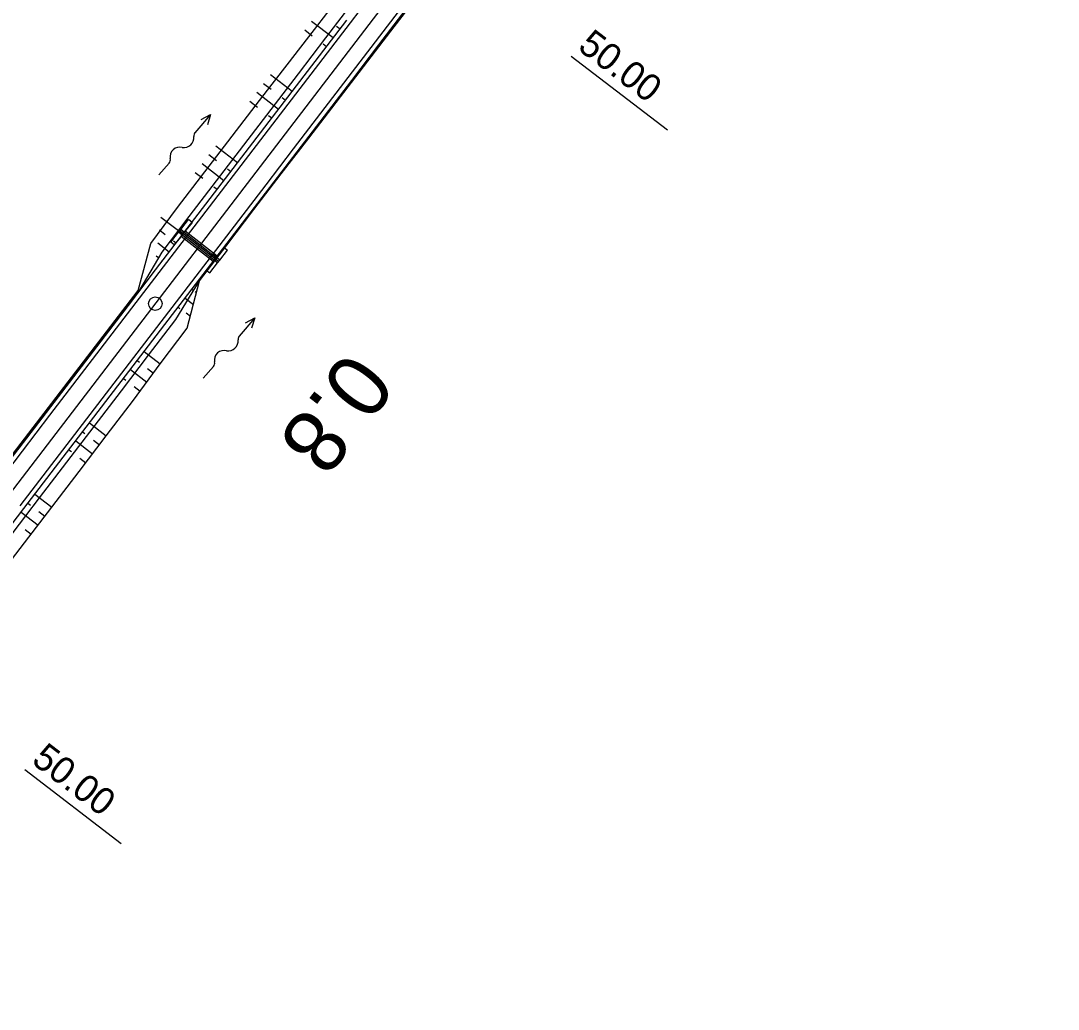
# Model space of a CAD drawing. Extents: x -481645 to -478728, y -1113199 to -1110710.
# Drawn here: x -479367.1 to -479251.7, y -1111289 to -1111179 of the extents above; entities that cross this region are included whole.
import ezdxf

# ---------------------------------------------------------------- set-up
doc = ezdxf.new("R2010")
doc.units = 0
for name, color, linetype in [('CP14_HATCH_SLOPE_L', 7, 'Continuous'), ('CP14_HECTOMETRY', 7, 'Continuous'), ('CP14_HLBODY', 7, 'Continuous'), ('CP14_ZPEVKRAJ', 7, 'Continuous'), ('CP1_HECTOMETRY', 7, 'Continuous'), ('O6_HATCH_SLOPE_L', 7, 'Continuous'), ('O6_HATCH_SLOPE_R', 7, 'Continuous'), ('O6_HLBODY', 7, 'Continuous'), ('O6_HRANA_TELESO', 7, 'Continuous'), ('O6_OSA', 7, 'Continuous'), ('O6_VOZOVKA', 7, 'Continuous'), ('O6_ZPEVKRAJ', 7, 'Continuous')]:
    doc.layers.add(name, color=color, linetype=linetype)

# ---------------------------------------------------------------- blocks, each defined once
blk = doc.blocks.new('A$C70B')
at = {"layer": 'CP14_HLBODY'}
for p, q in [((0.87, 0), (-0.87, 0)), ((6.86, 0.43), (7.97, 0)), ((7.97, 0), (5.28, 0)), ((7.97, 0), (6.86, -0.48))]:
    blk.add_line(p, q, dxfattribs=at)
for centre, radius, start, end in [((0.87, 0.58), 0.582, 269.6924, 322.7901), ((2.17, -0.42), 1.05, 24.4039, 142.0836), ((4.08, 0.59), 1.11, 210.8873, 317.3707), ((5.32, -0.64), 0.636, 85.9766, 131.7248)]:
    blk.add_arc(centre, radius, start, end, dxfattribs=at)
blk = doc.blocks.new('A$C716')
at = {"layer": 'CP14_ZPEVKRAJ'}
for p, q in [((-5.015, 2.333), (-4.471, 3.623)), ((-4.01, 3.428), (-4.471, 3.623)), ((-5.17, 1.964), (-5.015, 2.333)), ((-5.015, 2.333), (-0.383, 0.379)), ((-4.554, 2.138), (-5.015, 2.333)), ((-4.01, 3.428), (-4.554, 2.138)), ((-5.715, 0.674), (-5.17, 1.964)), ((-4.71, 1.77), (-5.254, 0.48)), ((-0.078, -0.184), (-5.171, 1.964)), ((-4.71, 1.77), (-5.17, 1.964)), ((0, 0), (-5.093, 2.148)), ((-4.768, 1.632), (-0.597, -0.128)), ((-0.325, 0.517), (-4.496, 2.277)), ((0.161, 1.669), (-0.383, 0.379)), ((0.078, 0.184), (0.622, 1.474)), ((0.161, 1.669), (0.622, 1.474)), ((-5.254, 0.48), (-5.715, 0.674)), ((-0.538, 0.01), (-1.083, -1.28)), ((-0.078, -0.184), (-0.999, 0.204)), ((0.078, 0.184), (-0.844, 0.573)), ((-0.538, 0.01), (-0.383, 0.379)), ((-0.078, -0.184), (0.078, 0.184)), ((-0.622, -1.474), (-0.078, -0.184)), ((-1.083, -1.28), (-0.622, -1.474))]:
    blk.add_line(p, q, dxfattribs=at)

msp = doc.modelspace()

# ---------------------------------------------------------------- linework, layer by layer
at = {"layer": 'CP14_HATCH_SLOPE_L'}
for p, q in [((-479325.29, -1111179.1), (-479325.23, -1111179.15)), ((-479325.18, -1111179.19), (-479325.18, -1111179.19)), ((-479329.09, -1111184.07), (-479328.99, -1111184.14)), ((-479329.85, -1111185.06), (-479329.8, -1111185.1)), ((-479329.75, -1111185.14), (-479329.75, -1111185.14)), ((-479331.37, -1111187.04), (-479331.32, -1111187.08)), ((-479330.61, -1111186.05), (-479330.51, -1111186.13)), ((-479331.27, -1111187.12), (-479331.27, -1111187.12)), ((-479335.17, -1111192.01), (-479335.08, -1111192.07)), ((-479336.69, -1111193.99), (-479336.6, -1111194.06)), ((-479335.93, -1111193), (-479335.88, -1111193.03)), ((-479335.84, -1111193.06), (-479335.84, -1111193.06)), ((-479337.45, -1111194.99), (-479337.41, -1111195.02)), ((-479337.36, -1111195.05), (-479337.36, -1111195.05)), ((-479342.01, -1111200.94), (-479341.97, -1111200.97)), ((-479341.24, -1111199.95), (-479341.17, -1111200.01)), ((-479342.77, -1111201.93), (-479342.68, -1111201.99)), ((-479341.93, -1111201), (-479341.93, -1111201)), ((-479343.53, -1111202.93), (-479343.48, -1111202.96)), ((-479343.44, -1111202.99), (-479343.44, -1111202.99)), ((-479348.08, -1111208.88), (-479347.99, -1111208.95)), ((-479347.32, -1111207.89), (-479347.23, -1111207.96)), ((-479348.84, -1111209.87), (-479347.91, -1111210.59)), ((-479347.73, -1111209.15), (-479347.57, -1111209.27)), ((-479349.6, -1111210.87), (-479349.41, -1111211.02)), ((-479348.73, -1111211.53), (-479348.25, -1111211.9)), ((-479353.4, -1111215.83), (-479351.6, -1111217.2)), ((-479354.16, -1111216.82), (-479353.91, -1111217.02)), ((-479354.92, -1111217.81), (-479353.09, -1111219.22)), ((-479353, -1111217.71), (-479352.35, -1111218.21)), ((-479355.68, -1111218.81), (-479355.42, -1111219.01)), ((-479354.49, -1111219.72), (-479353.83, -1111220.23)), ((-479359.48, -1111223.77), (-479357.6, -1111225.21)), ((-479360.24, -1111224.76), (-479359.98, -1111224.96)), ((-479361, -1111225.76), (-479359.12, -1111227.19)), ((-479359.04, -1111225.68), (-479358.36, -1111226.2)), ((-479361.76, -1111226.75), (-479361.49, -1111226.95)), ((-479360.55, -1111227.67), (-479359.88, -1111228.19)), ((-479365.56, -1111231.71), (-479363.68, -1111233.15)), ((-479366.32, -1111232.7), (-479366.05, -1111232.91)), ((-479367.08, -1111233.7), (-479365.19, -1111235.14)), ((-479365.11, -1111233.63), (-479364.43, -1111234.15)), ((-479366.63, -1111235.61), (-479365.95, -1111236.13))]:
    msp.add_line(p, q, dxfattribs=at)
at = {"layer": 'CP1_HECTOMETRY'}
msp.add_line((-479472.65, -1111367.92), (-479250.4, -1111077.57), dxfattribs=at)
at = {"layer": 'O6_HATCH_SLOPE_L'}
msp.add_circle((-479352.15, -1111210.49), 0.75, dxfattribs=at)
at = {"layer": 'O6_HATCH_SLOPE_R'}
for p, q in [((-479334.69, -1111180.71), (-479335.53, -1111180.07)), ((-479332.35, -1111180.93), (-479334.77, -1111179.08)), ((-479331.59, -1111179.94), (-479331.97, -1111179.65)), ((-479333.11, -1111181.92), (-479333.49, -1111181.63)), ((-479336.91, -1111186.88), (-479339.33, -1111185.03)), ((-479338.43, -1111188.87), (-479340.86, -1111187.01)), ((-479339.26, -1111186.66), (-479340.1, -1111186.02)), ((-479340.78, -1111188.65), (-479341.62, -1111188)), ((-479337.67, -1111187.88), (-479338.04, -1111187.59)), ((-479339.19, -1111189.86), (-479339.56, -1111189.58)), ((-479345.34, -1111194.6), (-479346.19, -1111193.95)), ((-479342.99, -1111194.82), (-479345.43, -1111192.96)), ((-479344.51, -1111196.81), (-479346.95, -1111194.94)), ((-479346.86, -1111196.58), (-479347.71, -1111195.93)), ((-479343.75, -1111195.82), (-479344.12, -1111195.53)), ((-479345.27, -1111197.8), (-479345.64, -1111197.52)), ((-479349.07, -1111202.76), (-479351.52, -1111200.89)), ((-479351.05, -1111202.82), (-479351.7, -1111202.32)), ((-479350.59, -1111204.75), (-479351.88, -1111203.76)), ((-479349.83, -1111203.76), (-479350.11, -1111203.54)), ((-479351.8, -1111205.4), (-479352.06, -1111205.2)), ((-479351.35, -1111205.74), (-479351.44, -1111205.67)), ((-479355.15, -1111210.71), (-479355.27, -1111210.61)), ((-479355.97, -1111211.65), (-479356.03, -1111211.6)), ((-479355.91, -1111211.7), (-479355.91, -1111211.7)), ((-479357.49, -1111213.63), (-479357.55, -1111213.59)), ((-479356.67, -1111212.69), (-479356.79, -1111212.6)), ((-479357.43, -1111213.68), (-479357.43, -1111213.68)), ((-479361.23, -1111218.65), (-479361.35, -1111218.55)), ((-479362.74, -1111220.63), (-479362.87, -1111220.54)), ((-479362.05, -1111219.59), (-479362.11, -1111219.54)), ((-479361.98, -1111219.64), (-479361.99, -1111219.64)), ((-479363.57, -1111221.57), (-479363.63, -1111221.53)), ((-479363.5, -1111221.62), (-479363.51, -1111221.62))]:
    msp.add_line(p, q, dxfattribs=at)
at = {"layer": 'O6_HLBODY'}
for p, q in [((-479305.88, -1111182.94), (-479295.16, -1111191.15)), ((-479366.66, -1111262.35), (-479355.94, -1111270.56))]:
    msp.add_line(p, q, dxfattribs=at)
at = {"layer": 'O6_HRANA_TELESO'}
for p, q in [((-479333.19, -1111180.93), (-479330.15, -1111176.96)), ((-479336.23, -1111184.9), (-479333.19, -1111180.93)), ((-479339.27, -1111188.87), (-479336.23, -1111184.9)), ((-479342.31, -1111192.84), (-479339.27, -1111188.87)), ((-479345.35, -1111196.81), (-479342.31, -1111192.84)), ((-479348.39, -1111200.78), (-479345.35, -1111196.81)), ((-479351.4, -1111204.77), (-479348.39, -1111200.78)), ((-479353.94, -1111209.12), (-479351.4, -1111204.77)), ((-479349.87, -1111212.24), (-479347.23, -1111207.96)), ((-479356.98, -1111213.09), (-479353.94, -1111209.12)), ((-479352.9, -1111216.21), (-479349.87, -1111212.24)), ((-479360.02, -1111217.06), (-479356.98, -1111213.09)), ((-479363.06, -1111221.03), (-479360.02, -1111217.06)), ((-479355.91, -1111220.2), (-479352.9, -1111216.21)), ((-479358.95, -1111224.18), (-479355.91, -1111220.2)), ((-479366.1, -1111225), (-479363.06, -1111221.03)), ((-479369.14, -1111228.97), (-479366.1, -1111225)), ((-479361.99, -1111228.15), (-479358.95, -1111224.18)), ((-479365.03, -1111232.11), (-479361.99, -1111228.15)), ((-479368.07, -1111236.09), (-479365.03, -1111232.11))]:
    msp.add_line(p, q, dxfattribs=at)
at = {"layer": 'O6_OSA'}
for p, q in [((-479334.44, -1111179.97), (-479331.39, -1111176.01)), ((-479325.94, -1111180.18), (-479322.89, -1111176.22)), ((-479337.49, -1111183.93), (-479334.44, -1111179.97)), ((-479328.99, -1111184.14), (-479325.94, -1111180.18)), ((-479340.54, -1111187.9), (-479337.49, -1111183.93)), ((-479332.03, -1111188.11), (-479328.99, -1111184.14)), ((-479343.59, -1111191.86), (-479340.54, -1111187.9)), ((-479335.08, -1111192.07), (-479332.03, -1111188.11)), ((-479346.64, -1111195.82), (-479343.59, -1111191.86)), ((-479338.13, -1111196.04), (-479335.08, -1111192.07)), ((-479349.68, -1111199.79), (-479346.64, -1111195.82)), ((-479341.17, -1111200.01), (-479338.13, -1111196.04)), ((-479352.65, -1111203.81), (-479349.68, -1111199.79)), ((-479344.2, -1111203.98), (-479341.17, -1111200.01)), ((-479354.06, -1111209.03), (-479352.65, -1111203.81)), ((-479347.23, -1111207.96), (-479344.2, -1111203.98)), ((-479348.59, -1111213.22), (-479347.23, -1111207.96)), ((-479357.09, -1111213.01), (-479354.06, -1111209.03)), ((-479360.13, -1111216.98), (-479357.09, -1111213.01)), ((-479351.6, -1111217.2), (-479348.59, -1111213.22)), ((-479363.17, -1111220.95), (-479360.13, -1111216.98)), ((-479354.57, -1111221.24), (-479351.6, -1111217.2)), ((-479366.21, -1111224.92), (-479363.17, -1111220.95)), ((-479357.6, -1111225.21), (-479354.57, -1111221.24)), ((-479369.25, -1111228.89), (-479366.21, -1111224.92)), ((-479360.64, -1111229.18), (-479357.6, -1111225.21)), ((-479363.68, -1111233.15), (-479360.64, -1111229.18)), ((-479366.71, -1111237.12), (-479363.68, -1111233.15)), ((-479369.77, -1111241.08), (-479366.71, -1111237.12))]:
    msp.add_line(p, q, dxfattribs=at)
at = {"layer": 'O6_VOZOVKA'}
for p, q in [((-479330.44, -1111179.25), (-479327.4, -1111175.28)), ((-479327.66, -1111181.37), (-479324.62, -1111177.4)), ((-479333.48, -1111183.22), (-479330.44, -1111179.25)), ((-479330.7, -1111185.34), (-479327.66, -1111181.37)), ((-479336.52, -1111187.19), (-479333.48, -1111183.22)), ((-479333.73, -1111189.31), (-479330.7, -1111185.34)), ((-479339.55, -1111191.16), (-479336.52, -1111187.19)), ((-479336.78, -1111193.28), (-479333.73, -1111189.31)), ((-479342.59, -1111195.13), (-479339.55, -1111191.16)), ((-479339.81, -1111197.26), (-479336.78, -1111193.28)), ((-479345.63, -1111199.1), (-479342.59, -1111195.13)), ((-479342.85, -1111201.23), (-479339.81, -1111197.26)), ((-479348.67, -1111203.07), (-479345.63, -1111199.1)), ((-479345.89, -1111205.2), (-479342.85, -1111201.23)), ((-479351.71, -1111207.04), (-479348.67, -1111203.07)), ((-479348.93, -1111209.17), (-479345.89, -1111205.2)), ((-479354.75, -1111211.01), (-479351.71, -1111207.04)), ((-479351.97, -1111213.14), (-479348.93, -1111209.17)), ((-479357.79, -1111214.98), (-479354.75, -1111211.01)), ((-479355.01, -1111217.11), (-479351.97, -1111213.14)), ((-479360.83, -1111218.95), (-479357.79, -1111214.98)), ((-479358.05, -1111221.08), (-479355.01, -1111217.11)), ((-479363.87, -1111222.92), (-479360.83, -1111218.95)), ((-479361.09, -1111225.05), (-479358.05, -1111221.08)), ((-479366.91, -1111226.89), (-479363.87, -1111222.92)), ((-479364.13, -1111229.02), (-479361.09, -1111225.05)), ((-479369.95, -1111230.86), (-479366.91, -1111226.89)), ((-479367.17, -1111232.99), (-479364.13, -1111229.02))]:
    msp.add_line(p, q, dxfattribs=at)
at = {"layer": 'O6_ZPEVKRAJ'}
for p, q in [((-479327.26, -1111181.68), (-479324.22, -1111177.71)), ((-479333.87, -1111182.91), (-479330.83, -1111178.94)), ((-479330.3, -1111185.65), (-479327.26, -1111181.68)), ((-479336.91, -1111186.88), (-479333.87, -1111182.91)), ((-479333.34, -1111189.62), (-479330.3, -1111185.65)), ((-479339.95, -1111190.85), (-479336.91, -1111186.88)), ((-479336.38, -1111193.59), (-479333.34, -1111189.62)), ((-479342.99, -1111194.82), (-479339.95, -1111190.85)), ((-479339.42, -1111197.56), (-479336.38, -1111193.59)), ((-479346.03, -1111198.79), (-479342.99, -1111194.82)), ((-479342.46, -1111201.53), (-479339.42, -1111197.56)), ((-479349.07, -1111202.76), (-479346.03, -1111198.79)), ((-479345.49, -1111205.5), (-479342.46, -1111201.53)), ((-479352.11, -1111206.74), (-479349.07, -1111202.76)), ((-479348.53, -1111209.47), (-479345.49, -1111205.5)), ((-479355.15, -1111210.71), (-479352.11, -1111206.74)), ((-479351.57, -1111213.44), (-479348.53, -1111209.47)), ((-479358.19, -1111214.68), (-479355.15, -1111210.71)), ((-479354.61, -1111217.41), (-479351.57, -1111213.44)), ((-479361.23, -1111218.65), (-479358.19, -1111214.68)), ((-479357.65, -1111221.38), (-479354.61, -1111217.41)), ((-479364.26, -1111222.62), (-479361.23, -1111218.65)), ((-479360.69, -1111225.35), (-479357.65, -1111221.38)), ((-479367.3, -1111226.59), (-479364.26, -1111222.62)), ((-479363.73, -1111229.32), (-479360.69, -1111225.35)), ((-479366.77, -1111233.29), (-479363.73, -1111229.32)), ((-479369.81, -1111237.26), (-479366.77, -1111233.29))]:
    msp.add_line(p, q, dxfattribs=at)

# ---------------------------------------------------------------- block references
at = {"layer": 'CP14_HECTOMETRY', "rotation": 49.50153353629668}
for p in [(-479351.18, -1111195.51), (-479346.25, -1111218.13)]:
    msp.add_blockref('A$C70B', p, dxfattribs=at)
at = {"layer": 'CP14_ZPEVKRAJ', "rotation": -15.313108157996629}
msp.add_blockref('A$C716', (-479345.1, -1111205.81), dxfattribs=at)

# ---------------------------------------------------------------- texts
at = {"layer": 'O6_HATCH_SLOPE_L'}
msp.add_text('0.8', height=7, rotation=232.5212, dxfattribs=at).set_placement((-479330.77, -1111215.47))
at = {"layer": 'O6_HLBODY'}
for p in [(-479305.27, -1111182.15), (-479366.05, -1111261.56)]:
    msp.add_text('50.00', height=3, rotation=322.5669, dxfattribs=at).set_placement(p)

doc.saveas('drawing.dxf')
